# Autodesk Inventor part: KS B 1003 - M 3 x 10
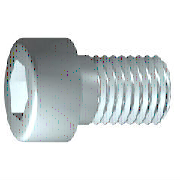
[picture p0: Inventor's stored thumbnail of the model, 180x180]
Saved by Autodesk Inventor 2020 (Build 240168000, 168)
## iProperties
Created: 2019-01
Part Number: KS B 1003 - M 3 x 10
Material: Acier, doux
Description: Vis à tôle à tête hexagonale
Document SubType Name: Modeling
Standard: KS B 1003
Designer: bruno
Standards Organization: KS
Language: fr-FR
Size Designation: M 3 x 10
Categories: <MemberInstance><Categories><Category DisplayName="Visserie" InternalName="e4da775c-781d-43d5-af7c-5136215cf5a6" Mnemonic="FSTN"><Category DisplayName="Vis" Int
Density: 7.85 g/cm^3
Appearance: Semi-poli
IsCustomPart: 0
Author: bruno
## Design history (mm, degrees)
sketch "Esquisse1"
  geometry: L1 (-0.867, 0)-(10, 0); L2 (10, 0)-(10, 1.5); L3 (10, 1.5)-(1.25, 1.5); L4 (1.25, 1.5)-(0.943, 1.5); L5 (0.943, 1.5)-(0, 1.5); L6 (0, 1.5)-(0, 2.75); L7 (0, 2.75)-(-3, 2.75); L8 (-3, 2.75)-(-3, 1.443); L9 (-3, 1.443)-(-1.7, 1.443); L10 (-1.7, 1.443)-(-0.867, 0); L11 (-5.6, 0)-(12.6, 0) reference; L12 (0, -0.55)-(0, 3.3) reference; L13 (1.25, 1.5)-(0, 1.5)
  constraints: 22 end point, 6 parallel, 2 collinear, 2 perpendicular, 1 horizontal, 1 point on line
  dimensions: "d1" = 8.75 distance from line of L3.end L2 (= GEL); "d2" = 0.30683 distance of L4.end L3.end (computed from GAL); "d3" = 3 distance between parallel lines of L8 L6 (= KOH); "d4" = 1.3 distance of L8.end L9.end (= INTI); "d5" = 60 deg angle of L10 L1; "d6" = 3 diameter of L3 L1 (= GD); "d7" = 3 diameter of L5 L1 (= BDM); "d8" = 2.88675 diameter of L9 L1 (= 1.1547 x SW); "d9" = 5.5 diameter of L7 L1 (= KOD); "d26" = 10 distance between parallel lines of L12 L2 (= NLG)
revolve "Corps" sketch "Esquisse1" stored, may be unused: angle "d10" = 90 deg
sketch "Esquisse2"
  geometry: L1 (0, -3.85)-(0, 3.85) reference; L2 (-3.85, 0)-(3.85, 0) reference; L3 (1.443, 0)-(0.722, -1.25); L4 (0.722, -1.25)-(-0.722, -1.25); L5 (-0.722, -1.25)-(-1.443, 0); L6 (-1.443, 0)-(-0.722, 1.25); L7 (-0.722, 1.25)-(0.722, 1.25); L8 (0.722, 1.25)-(1.443, 0); 2 further points
  constraints: 12 end point, 1 coincident, 1 horizontal alignment, 1 point on line, 12 other
extrude "Rainure" join sketch "Esquisse2" stored distance "d11" = 10; taper "d12" = 0 deg
workplane "Work Plane1"
fillet "Fillet2" dims "d30" = 0.1 (= R)
body "Solid1"
fillet "Congé1" dims "d17" = 0.3 (= RR)
feature "Filetage" dims "d13" = 8.75 (= GEL), "d14" = 0
chamfer "Chanfrein1" distance "d15" = 0.30673 (= -0.5 x SPD + 0.5 x GD); stored, may be unused: second distance "d16" = 0.30673 (= GUL), angle "d27" = 45 deg
other parameters: "GD" = 3 (= NND) [user parameter; used in 2 equation terms], "NLG" = 10 [user parameter; used in 1 equation term], "GEL" = 8.75 [user parameter; used in 2 equation terms], "KOD" = 5.5 [user parameter; used in 1 equation term], "KOH" = 3 [user parameter; used in 1 equation term], "INTI" = 1.3 [user parameter; used in 1 equation term], "GAL" = 0.30673 (= 0.61345 x PTC) [user parameter; used in 1 equation term], "GUL" = 0.30673 (= 0.61345 x PTC) [user parameter; used in 1 equation term], "BDM" = 3 (= NND) [user parameter; used in 1 equation term], "SW" = 2.5 [user parameter; used in 2 equation terms], "RR" = 0.3 [user parameter; used in 1 equation term], "SPD" = 2.38655 (= NND - 1.2269 x PTC) [user parameter; used in 1 equation term], "d19" = 0, "d28" = 0, "d29" = 0, "R" = 0.1 [user parameter; used in 1 equation term], "PHH" = 0.1 [user parameter], "GD1" = 2.38655 (= THREADDIA - 1.2269 x PTC) [user parameter], "THREADDIA" = 3 [user parameter; used in 1 equation term], "FAWI" = 45 deg [user parameter], "PTC" = 0.5 [user parameter; used in 5 equation terms], "NND" = 3 [user parameter; used in 3 equation terms], "TOA" = 30 deg [user parameter], "E0" = 2.8875 (= 1.155 x SW) [user parameter]
